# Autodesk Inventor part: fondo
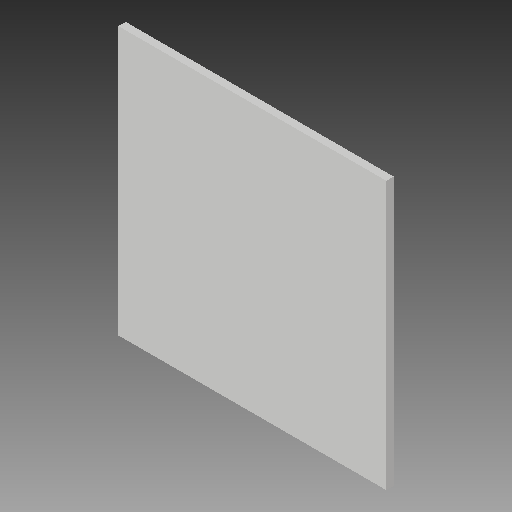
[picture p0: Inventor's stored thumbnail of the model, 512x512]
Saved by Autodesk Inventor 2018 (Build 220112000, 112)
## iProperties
Created: 2019-03
Part Number: fondo
Material: Generic
Document SubType Name: Modeling
Designer: vpimentel
Density: 1 g/cm^3
Appearance: Default
Author: vpimentel
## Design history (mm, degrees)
sketch "Sketch1"
  geometry: L1 (0, 0)-(550, 0) reference; L2 (550, 0)-(550, 2.9) reference; L3 (0, 2.9)-(550, 2.9) reference; L4 (0, 0)-(0, 2.9) reference; L5 (163.55, 2.9)-(163.55, 251.45) reference; L6 (163.55, 251.45)-(160.65, 251.45) reference; L7 (160.65, 2.9)-(160.65, 251.45) reference; L8 (163.55, 2.9)-(160.65, 2.9) reference; L9 (163.55, -248.55)-(163.55, 0) reference; L10 (163.55, 0)-(160.65, 0) reference; L11 (160.65, -248.55)-(160.65, 0) reference; L12 (163.55, -248.55)-(160.65, -248.55) reference; L13 (273.55, -273.55)-(273.55, 0) reference; L14 (273.55, -273.55)-(276.45, -273.55) reference; L15 (276.45, 0)-(276.45, -273.55) reference; L16 (273.55, 0)-(276.45, 0) reference; L17 (273.55, 2.9)-(273.55, 276.45) reference; L18 (273.55, 2.9)-(276.45, 2.9) reference; L19 (276.45, 276.45)-(276.45, 2.9) reference; L20 (273.55, 276.45)-(276.45, 276.45) reference; L21 (273.55, 115.8)-(163.55, 115.8) reference; L22 (163.55, 115.8)-(163.55, 112.9) reference; L23 (273.55, 112.9)-(163.55, 112.9) reference; L24 (273.55, 115.8)-(273.55, 112.9) reference; L25 (163.55, 112.9)-(273.55, 112.9); L26 (273.55, 112.9)-(273.55, 2.9); L27 (273.55, 2.9)-(163.55, 2.9); L28 (163.55, 2.9)-(163.55, 112.9)
  constraints: 8 end point, 2 parallel, 1 horizontal, 1 perpendicular
extrude "Extrusion1" new body sketch "Sketch1" distance "d0" = 3; taper "d1" = 0 deg
body "Solid1"
node "Reference1"
node "Reference2"
node "Reference3"
node "Reference4"
node "Reference5"
node "Reference6"
